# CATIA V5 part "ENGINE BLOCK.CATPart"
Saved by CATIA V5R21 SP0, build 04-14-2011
Part number: Part1.2.4
Bounding box of the stored display mesh (mm): x -410 to 0, y -112.5 to 0, z 0 to 260
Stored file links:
  G:\CATIA\PROJECT__01\ENGINE BLOCK.CATPart
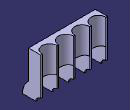
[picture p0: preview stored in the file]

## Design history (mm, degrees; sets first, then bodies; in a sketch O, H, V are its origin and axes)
Body1 (main body)
  Sketch1 on yz-plane, origin (0, 0, 0), H (0, 1, 0), V (0, 0, 1)
    arc A1 centre (0, 0) radius 112.5 from (-75, 83.8525) to (-112.5, 0) ccw
    line L1 (0, 0) -> (0, 260)
    line L2 (0, 260) -> (-75, 260)
    line L3 (-75, 260) -> (-75, 83.8525)
    line L4 (0, 0) -> (-112.5, 0)
    radius A1 = 112.5
    length L1 = 260
    length L2 = 75
    vertical: L1 V, L3 V
    horizontal: L2 H, L4 H
  Pad1: profile Sketch1, direction (-1, 0, 0), length 410
  Plane1: type Offset, RefPlane start face of Pad1, Offset 10
  Sketch2 on Plane1, origin (-10, 0, 0), H (0, -1, 0), V (0, 0, 1)
    circle A1 centre (0, 0) radius 102.5
    radius A1 = 102.5
  Pocket1: profile Sketch2, direction (-1, 0, 0), length 90
  Sketch3 on face of Pad1 from Sketch1.L2, origin (0, 0, 260), H (1, 0, 0), V (0, 1, 0)
    circle A1 centre (-55, -1.6512) radius 45
    reference projected line E1 (-100, -102.5) -> (-100, 102.5) from edge [end face of Pocket1 | face of Pocket1 from Sketch2.A1]
    reference intersected line E2 through (-10, 0) direction (0, -1) from Plane1
    tangency: A1 E1, A1 E2
  Pocket2: profile Sketch3, direction (0, 0, -1), through (limit type 6)
  RectPattern1: of Pocket1, Pocket2, direction 1 instances 4, spacing 100, along edge [face of Pad1 from Sketch1.L1 | face of Pad1 from Sketch1.L2]
  Sketch4 on start face of Pad1, origin (0, 0, 0), H (0, 1, 0), V (0, 0, 1)
    circle A1 centre (0, 0) radius 31
    radius A1 = 31
  Pocket3: profile Sketch4, direction (-1, 0, 0), through (limit type 3)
